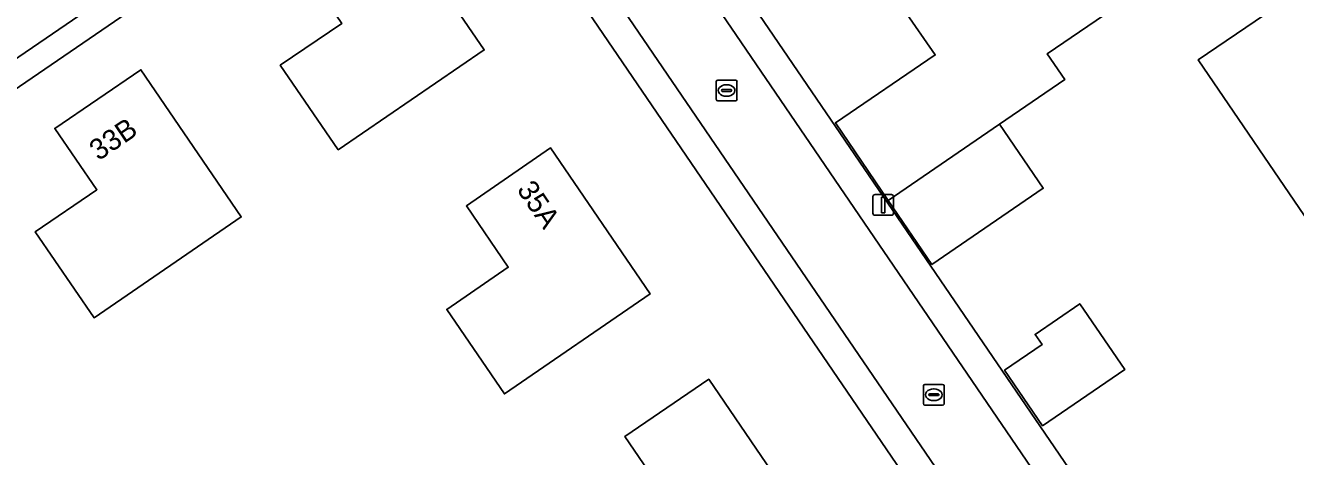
# Model space of a CAD drawing. Extents: x 155275 to 156265, y 382654 to 383635.
# Drawn here: x 155428.8 to 155490, y 383258.3 to 383279.1 of the extents above; entities that cross this region are included whole.
import ezdxf

# ---------------------------------------------------------------- set-up
doc = ezdxf.new("R2010")
doc.units = 0
for name, color, linetype in [('IMGEO_Erf', 7, 'Continuous'), ('IMGEO_Kolk', 7, 'Continuous'), ('IMGEO_Lichtmast', 7, 'Continuous'), ('IMGEO_Pand', 7, 'Continuous'), ('IMGEO_Pand_nummerreeks', 7, 'Continuous'), ('IMGEO_Pand_overbouw', 7, 'Continuous'), ('IMGEO_Parkeervlak_open', 7, 'Continuous'), ('IMGEO_Rijbaan_lokaal_open', 7, 'Continuous'), ('IMGEO_Voetpad_open', 7, 'Continuous')]:
    doc.layers.add(name, color=color, linetype=linetype)

msp = doc.modelspace()

# ---------------------------------------------------------------- linework, layer by layer
at = {"layer": 'IMGEO_Erf'}
for points in [[(155498.922, 383291.025), (155490.365, 383303.561), (155484.692, 383311.871), (155483.519, 383313.595), (155458.608, 383296.58), (155454.563, 383293.76), (155518.365, 383200.253), (155523.731, 383203.931), (155542.221, 383216.713), (155538.669, 383221.857), (155525.357, 383212.738), (155524.015, 383214.705), (155523.982, 383214.682), (155523.259, 383215.732), (155518.011, 383212.12), (155515.657, 383215.542), (155521.261, 383219.398), (155522.097, 383218.189), (155539.024, 383229.787), (155546.127, 383219.41), (155547.42, 383220.262)], [(155478.068, 383277.739), (155478.914, 383276.501), (155475.766, 383274.346), (155477.88, 383271.261), (155472.514, 383267.589), (155470.402, 383270.675), (155467.861, 383274.42), (155472.672, 383277.696), (155471.178, 383279.852), (155483.314, 383288.146), (155485.141, 383289.394), (155482.779, 383292.843), (155490.457, 383298.092), (155493.615, 383293.483), (155489.973, 383290.987), (155491.346, 383288.985), (155490.44, 383288.371), (155490.41, 383288.351), (155491.433, 383286.863)], [(155443.885, 383273.121), (155441.09, 383277.194), (155444.064, 383279.21), (155442.041, 383282.191), (155444.526, 383283.883), (155446.112, 383284.963), (155450.93, 383277.937)], [(155432.114, 383265.021), (155429.277, 383269.165), (155432.256, 383271.193), (155430.222, 383274.149), (155434.371, 383276.976), (155439.209, 383269.878)], [(155449.123, 383265.421), (155452.088, 383267.451), (155450.068, 383270.414), (155454.126, 383273.206), (155458.921, 383266.167), (155451.904, 383261.344)], [(155481.808, 383262.522), (155477.847, 383259.811), (155476.015, 383262.484), (155477.823, 383263.721), (155477.483, 383264.216), (155479.637, 383265.69)], [(155456.765, 383254.271), (155459.746, 383256.3), (155457.704, 383259.287), (155461.754, 383262.055), (155466.566, 383255.008), (155459.548, 383250.186)]]:
    msp.add_lwpolyline(points, close=True, dxfattribs=at)
msp.add_lwpolyline([(155428.923, 383238.236), (155433.772, 383231.088), (155444.08, 383215.943), (155444.194, 383215.772), (155445.521, 383213.792), (155474.854, 383170.583), (155512.727, 383196.487), (155448.882, 383290.128), (155420.301, 383270.554)], dxfattribs=at)
at = {"layer": 'IMGEO_Kolk'}
for p, q in [((155462.113, 383275.551), (155462.113, 383276.403)), ((155462.188, 383276.477), (155463.04, 383276.477)), ((155462.601, 383276.257), (155462.626, 383276.257)), ((155463.114, 383276.403), (155463.114, 383275.551)), ((155462.372, 383275.971), (155462.372, 383275.983)), ((155462.81, 383275.934), (155462.412, 383275.934)), ((155462.415, 383276.02), (155462.813, 383276.02)), ((155462.624, 383275.697), (155462.599, 383275.697)), ((155462.856, 383275.983), (155462.856, 383275.971)), ((155463.04, 383275.477), (155462.188, 383275.477)), ((155472.101, 383260.879), (155472.101, 383261.731)), ((155472.176, 383261.805), (155473.028, 383261.805)), ((155472.589, 383261.585), (155472.614, 383261.585)), ((155473.102, 383261.731), (155473.102, 383260.879)), ((155472.36, 383261.299), (155472.36, 383261.311)), ((155472.798, 383261.262), (155472.4, 383261.262)), ((155472.403, 383261.348), (155472.801, 383261.348)), ((155472.612, 383261.025), (155472.587, 383261.025)), ((155472.844, 383261.311), (155472.844, 383261.299)), ((155473.028, 383260.805), (155472.176, 383260.805))]:
    msp.add_line(p, q, dxfattribs=at)
for points in [[(155462.113, 383275.551), (155462.113, 383276.403)], [(155462.188, 383276.477), (155463.04, 383276.477)], [(155463.114, 383276.403), (155463.114, 383275.551)], [(155463.04, 383275.477), (155462.188, 383275.477)], [(155472.101, 383260.879), (155472.101, 383261.731)], [(155472.176, 383261.805), (155473.028, 383261.805)], [(155473.102, 383261.731), (155473.102, 383260.879)], [(155473.028, 383260.805), (155472.176, 383260.805)]]:
    msp.add_lwpolyline(points, dxfattribs=at)
for centre, radius, start, end in [((155462.19, 383276.401), 0.0765, 91.55205, 178.44795), ((155462.19, 383276.401), 0.0765, 91.55205, 178.44795), ((155463.038, 383276.401), 0.0765, 1.55205, 88.44795), ((155463.038, 383276.401), 0.0765, 1.55205, 88.44795), ((155462.412, 383275.98), 0.0403, 85.87752, 175.75265), ((155462.409, 383275.97), 0.0366, 178.93798, 274.71019), ((155462.813, 383275.977), 0.043, 264.86636, 352.45326), ((155462.817, 383275.982), 0.0386, 1.73085, 96.63898), ((155462.19, 383275.553), 0.0765, 181.55205, 268.44795), ((155462.19, 383275.553), 0.0765, 181.55205, 268.44795), ((155463.038, 383275.553), 0.0765, 271.55205, 358.44795), ((155463.038, 383275.553), 0.0765, 271.55205, 358.44795), ((155472.178, 383261.729), 0.0765, 91.55205, 178.44795), ((155472.178, 383261.729), 0.0765, 91.55205, 178.44795), ((155473.026, 383261.729), 0.0765, 1.55205, 88.44795), ((155473.026, 383261.729), 0.0765, 1.55205, 88.44795), ((155472.178, 383260.881), 0.0765, 181.55205, 268.44795), ((155472.178, 383260.881), 0.0765, 181.55205, 268.44795), ((155472.4, 383261.308), 0.0403, 85.87752, 175.75265), ((155472.397, 383261.298), 0.0366, 178.93798, 274.71019), ((155472.801, 383261.305), 0.043, 264.86636, 352.45326), ((155472.805, 383261.31), 0.0386, 1.73085, 96.63898), ((155473.026, 383260.881), 0.0765, 271.55205, 358.44795), ((155473.026, 383260.881), 0.0765, 271.55205, 358.44795)]:
    msp.add_arc(centre, radius, start, end, dxfattribs=at)
for centre, major_axis, ratio, start_param, end_param in [((155462.6, 383275.977), (-0.387, 0.002), 0.722429, 4.712389, 7.853982), ((155462.625, 383275.977), (-0.39, 0.002), 0.717154, 1.570796, 4.712389), ((155472.588, 383261.305), (-0.387, 0.002), 0.722429, 4.712389, 7.853982), ((155472.613, 383261.305), (-0.39, 0.002), 0.717154, 1.570796, 4.712389)]:
    msp.add_ellipse(centre, major_axis=major_axis, ratio=ratio, start_param=start_param, end_param=end_param, dxfattribs=at)
at = {"layer": 'IMGEO_Lichtmast'}
for p, q in [((155469.669, 383270.059), (155469.669, 383270.859)), ((155469.669, 383270.859), (155469.669, 383270.059)), ((155469.769, 383270.959), (155470.559, 383270.959)), ((155470.559, 383270.959), (155469.769, 383270.959)), ((155470.659, 383270.859), (155470.659, 383270.059)), ((155470.659, 383270.059), (155470.659, 383270.859)), ((155470.559, 383269.959), (155469.769, 383269.959)), ((155469.769, 383269.959), (155470.559, 383269.959))]:
    msp.add_line(p, q, dxfattribs=at)
msp.add_lwpolyline([(155470.089, 383270.834), (155470.239, 383270.834), (155470.239, 383270.084), (155470.089, 383270.084), (155470.089, 383270.834)], dxfattribs=at)
for centre, start, end in [((155469.769, 383270.859), 90, 180), ((155469.769, 383270.859), 90, 180), ((155470.559, 383270.859), 0, 90), ((155470.559, 383270.859), 360, 90), ((155469.769, 383270.059), 180, 270), ((155469.769, 383270.059), 180, 270), ((155470.559, 383270.059), 270, 0), ((155470.559, 383270.059), 270, 0)]:
    msp.add_arc(centre, 0.1, start, end, dxfattribs=at)
at = {"layer": 'IMGEO_Pand'}
for points in [[(155491.433, 383286.863), (155490.41, 383288.351), (155490.44, 383288.371), (155491.346, 383288.985), (155489.973, 383290.987), (155493.615, 383293.483), (155490.457, 383298.092), (155482.779, 383292.843), (155485.141, 383289.394), (155483.314, 383288.146), (155471.178, 383279.852), (155472.672, 383277.696), (155467.861, 383274.42), (155470.402, 383270.675), (155475.766, 383274.346), (155478.914, 383276.501), (155478.068, 383277.739)], [(155446.112, 383284.963), (155444.526, 383283.883), (155442.041, 383282.191), (155444.064, 383279.21), (155441.09, 383277.194), (155443.885, 383273.121), (155450.93, 383277.937)], [(155434.371, 383276.976), (155430.222, 383274.149), (155432.256, 383271.193), (155429.277, 383269.165), (155432.114, 383265.021), (155439.209, 383269.878)], [(155475.766, 383274.346), (155470.402, 383270.675), (155472.514, 383267.589), (155477.88, 383271.261)], [(155454.126, 383273.206), (155450.068, 383270.414), (155452.088, 383267.451), (155449.123, 383265.421), (155451.904, 383261.344), (155458.921, 383266.167)], [(155477.847, 383259.811), (155481.808, 383262.522), (155479.637, 383265.69), (155477.483, 383264.216), (155477.823, 383263.721), (155476.015, 383262.484)], [(155461.754, 383262.055), (155457.704, 383259.287), (155459.746, 383256.3), (155456.765, 383254.271), (155459.548, 383250.186), (155466.566, 383255.008)]]:
    msp.add_lwpolyline(points, close=True, dxfattribs=at)
at = {"layer": 'IMGEO_Pand_overbouw'}
msp.add_lwpolyline([(155491.29, 383281.5), (155485.354, 383277.463), (155490.963, 383269.23), (155496.909, 383273.269)], close=True, dxfattribs=at)
at = {"layer": 'IMGEO_Parkeervlak_open'}
msp.add_lwpolyline([(155433.668, 383281.15), (155431.252, 383284.656), (155430.818, 383285.286), (155424.682, 383281.084), (155425.124, 383280.435), (155427.506, 383276.937)], close=True, dxfattribs=at)
at = {"layer": 'IMGEO_Rijbaan_lokaal_open'}
for points in [[(155518.343, 383197.603), (155517.119, 383199.399), (155453.361, 383292.898)], [(155448.903, 383292.685), (155450.079, 383290.961), (155513.95, 383197.324), (155515.231, 383195.446)]]:
    msp.add_lwpolyline(points, dxfattribs=at)
at = {"layer": 'IMGEO_Voetpad_open'}
for points in [[(155454.563, 383293.76), (155453.361, 383292.898), (155517.119, 383199.399), (155518.365, 383200.253)], [(155450.079, 383290.961), (155448.882, 383290.128), (155512.727, 383196.487), (155513.95, 383197.324)]]:
    msp.add_lwpolyline(points, close=True, dxfattribs=at)
msp.add_lwpolyline([(155447.524, 383292.099), (155448.211, 383291.07), (155441.057, 383286.203), (155436.959, 383283.394), (155433.668, 383281.15), (155427.506, 383276.937), (155419.66, 383271.549), (155420.301, 383270.554), (155448.882, 383290.128)], dxfattribs=at)

# ---------------------------------------------------------------- texts
at = {"layer": 'IMGEO_Pand_nummerreeks'}
for s, rotation, p in [('33B', 34.26861, (155432.33, 383272.56)), ('35A', 304.26267, (155452.47, 383271.196))]:
    msp.add_text(s, height=1, rotation=rotation, dxfattribs=at).set_placement(p)

doc.saveas('drawing.dxf')
